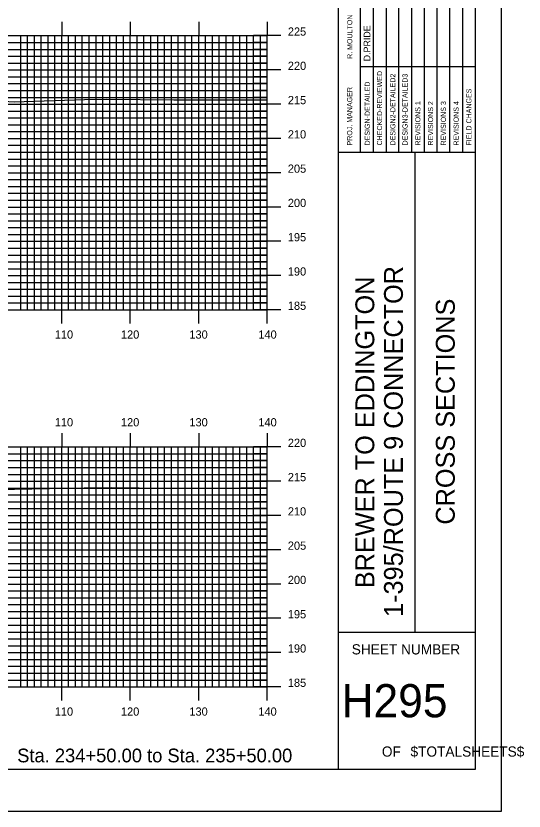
# Model space of a CAD drawing. Extents: x 1800355 to 1800699, y 442591 to 442811.
# Drawn here: x 1800624.3 to 1800698.5, y 442590.5 to 442706.6 of the extents above; entities that cross this region are included whole.
import ezdxf

# ---------------------------------------------------------------- set-up
doc = ezdxf.new("R2010")
doc.units = 0
for name, color, linetype in [('BORDER', 7, 'Continuous'), ('H_V ANNOTATION', 7, 'Continuous'), ('MAJOR', 7, 'Continuous'), ('MINOR', 7, 'Continuous'), ('PLOT BOUNDARY', 7, 'Continuous'), ('S_Roadway_Centerline', 7, 'Continuous')]:
    doc.layers.add(name, color=color, linetype=linetype)

msp = doc.modelspace()

# ---------------------------------------------------------------- linework, layer by layer
at = {"layer": 'BORDER'}
for p, q in [((1800671.44, 442596.67), (1800671.44, 442806.67)), ((1800671.44, 442686.67), (1800691.44, 442686.67)), ((1800682.62, 442616.67), (1800682.62, 442686.67)), ((1800671.44, 442616.67), (1800691.44, 442616.67))]:
    msp.add_line(p, q, dxfattribs=at)
msp.add_lwpolyline([(1800371.44, 442596.67), (1800691.44, 442596.67), (1800691.44, 442806.67), (1800371.44, 442806.67)], close=True, dxfattribs=at)
for points in [[(1800676.53, 442686.68), (1800676.53, 442721.67)], [(1800678.39, 442721.67), (1800678.39, 442686.68)], [(1800680.26, 442686.68), (1800680.26, 442721.67)], [(1800682.12, 442686.68), (1800682.12, 442721.67)], [(1800683.98, 442686.68), (1800683.98, 442721.67)], [(1800685.85, 442686.68), (1800685.85, 442721.67)], [(1800687.71, 442686.68), (1800687.71, 442721.67)], [(1800689.57, 442686.68), (1800689.57, 442721.67)], [(1800674.67, 442686.68), (1800674.67, 442720.26)], [(1800674.67, 442699.17), (1800691.44, 442699.17)]]:
    msp.add_lwpolyline(points, dxfattribs=at)
at = {"layer": 'MAJOR'}
for p, q in [((1800631.04, 442705.67), (1800631.04, 442703.67)), ((1800641.04, 442705.67), (1800641.04, 442703.67)), ((1800651.04, 442705.67), (1800651.04, 442703.67)), ((1800661.04, 442705.67), (1800661.04, 442703.67)), ((1800381.04, 442703.67), (1800661.04, 442703.67)), ((1800381.04, 442703.67), (1800661.04, 442703.67)), ((1800631.04, 442663.67), (1800631.04, 442703.67)), ((1800641.04, 442663.67), (1800641.04, 442703.67)), ((1800651.04, 442663.67), (1800651.04, 442703.67)), ((1800663.04, 442703.67), (1800659.03, 442703.67)), ((1800661.04, 442663.67), (1800661.04, 442703.67)), ((1800661.04, 442663.67), (1800661.04, 442703.67)), ((1800381.04, 442698.67), (1800661.04, 442698.67)), ((1800663.04, 442698.67), (1800659.03, 442698.67)), ((1800381.04, 442693.67), (1800661.04, 442693.67)), ((1800663.04, 442693.67), (1800659.03, 442693.67)), ((1800381.04, 442688.67), (1800661.04, 442688.67)), ((1800663.04, 442688.67), (1800659.03, 442688.67)), ((1800381.04, 442683.67), (1800661.04, 442683.67)), ((1800663.04, 442683.67), (1800659.03, 442683.67)), ((1800381.04, 442678.67), (1800661.04, 442678.67)), ((1800663.04, 442678.67), (1800659.03, 442678.67)), ((1800381.04, 442673.67), (1800661.04, 442673.67)), ((1800663.04, 442673.67), (1800659.03, 442673.67)), ((1800381.04, 442668.67), (1800661.04, 442668.67)), ((1800663.04, 442668.67), (1800659.03, 442668.67)), ((1800381.04, 442663.67), (1800661.04, 442663.67)), ((1800381.04, 442663.67), (1800661.04, 442663.67)), ((1800631.04, 442661.66), (1800631.04, 442663.67)), ((1800641.04, 442661.66), (1800641.04, 442663.67)), ((1800651.04, 442661.66), (1800651.04, 442663.67)), ((1800663.04, 442663.67), (1800659.03, 442663.67)), ((1800661.04, 442661.66), (1800661.04, 442663.67)), ((1800631.04, 442645.67), (1800631.04, 442643.67)), ((1800641.04, 442645.67), (1800641.04, 442643.67)), ((1800651.04, 442645.67), (1800651.04, 442643.67)), ((1800661.04, 442645.67), (1800661.04, 442643.67)), ((1800381.04, 442643.67), (1800661.04, 442643.67)), ((1800381.04, 442643.67), (1800661.04, 442643.67)), ((1800631.04, 442608.67), (1800631.04, 442643.67)), ((1800641.04, 442608.67), (1800641.04, 442643.67)), ((1800651.04, 442608.67), (1800651.04, 442643.67)), ((1800663.04, 442643.67), (1800659.03, 442643.67)), ((1800661.04, 442608.67), (1800661.04, 442643.67)), ((1800661.04, 442608.67), (1800661.04, 442643.67)), ((1800381.04, 442638.67), (1800661.04, 442638.67)), ((1800663.04, 442638.67), (1800659.03, 442638.67)), ((1800381.04, 442633.67), (1800661.04, 442633.67)), ((1800663.04, 442633.67), (1800659.03, 442633.67)), ((1800381.04, 442628.67), (1800661.04, 442628.67)), ((1800663.04, 442628.67), (1800659.03, 442628.67)), ((1800381.04, 442623.67), (1800661.04, 442623.67)), ((1800663.04, 442623.67), (1800659.03, 442623.67)), ((1800381.04, 442618.67), (1800661.04, 442618.67)), ((1800663.04, 442618.67), (1800659.03, 442618.67)), ((1800381.04, 442613.67), (1800661.04, 442613.67)), ((1800663.04, 442613.67), (1800659.03, 442613.67)), ((1800381.04, 442608.67), (1800661.04, 442608.67)), ((1800381.04, 442608.67), (1800661.04, 442608.67)), ((1800631.04, 442606.66), (1800631.04, 442608.67)), ((1800641.04, 442606.66), (1800641.04, 442608.67)), ((1800651.04, 442606.66), (1800651.04, 442608.67)), ((1800663.04, 442608.67), (1800659.03, 442608.67)), ((1800661.04, 442606.66), (1800661.04, 442608.67))]:
    msp.add_line(p, q, dxfattribs=at)
at = {"layer": 'MINOR'}
for p, q in [((1800625.04, 442663.67), (1800625.04, 442703.67)), ((1800626.04, 442663.67), (1800626.04, 442703.67)), ((1800627.04, 442663.67), (1800627.04, 442703.67)), ((1800628.04, 442663.67), (1800628.04, 442703.67)), ((1800629.04, 442663.67), (1800629.04, 442703.67)), ((1800630.04, 442663.67), (1800630.04, 442703.67)), ((1800632.04, 442663.67), (1800632.04, 442703.67)), ((1800633.04, 442663.67), (1800633.04, 442703.67)), ((1800634.04, 442663.67), (1800634.04, 442703.67)), ((1800635.04, 442663.67), (1800635.04, 442703.67)), ((1800636.04, 442663.67), (1800636.04, 442703.67)), ((1800637.04, 442663.67), (1800637.04, 442703.67)), ((1800638.04, 442663.67), (1800638.04, 442703.67)), ((1800639.04, 442663.67), (1800639.04, 442703.67)), ((1800640.04, 442663.67), (1800640.04, 442703.67)), ((1800642.04, 442663.67), (1800642.04, 442703.67)), ((1800643.04, 442663.67), (1800643.04, 442703.67)), ((1800644.04, 442663.67), (1800644.04, 442703.67)), ((1800645.04, 442663.67), (1800645.04, 442703.67)), ((1800646.04, 442663.67), (1800646.04, 442703.67)), ((1800647.04, 442663.67), (1800647.04, 442703.67)), ((1800648.04, 442663.67), (1800648.04, 442703.67)), ((1800649.04, 442663.67), (1800649.04, 442703.67)), ((1800650.04, 442663.67), (1800650.04, 442703.67)), ((1800652.04, 442663.67), (1800652.04, 442703.67)), ((1800653.04, 442663.67), (1800653.04, 442703.67)), ((1800654.04, 442663.67), (1800654.04, 442703.67)), ((1800655.04, 442663.67), (1800655.04, 442703.67)), ((1800656.04, 442663.67), (1800656.04, 442703.67)), ((1800657.04, 442663.67), (1800657.04, 442703.67)), ((1800658.04, 442663.67), (1800658.04, 442703.67)), ((1800659.04, 442663.67), (1800659.04, 442703.67)), ((1800660.04, 442663.67), (1800660.04, 442703.67)), ((1800381.04, 442702.67), (1800661.04, 442702.67)), ((1800661.04, 442702.67), (1800659.03, 442702.67)), ((1800381.04, 442701.67), (1800661.04, 442701.67)), ((1800381.04, 442700.67), (1800661.04, 442700.67)), ((1800661.04, 442701.67), (1800659.03, 442701.67)), ((1800661.04, 442700.67), (1800659.03, 442700.67)), ((1800381.04, 442699.67), (1800661.04, 442699.67)), ((1800661.04, 442699.67), (1800659.03, 442699.67)), ((1800381.04, 442697.67), (1800661.04, 442697.67)), ((1800661.04, 442697.67), (1800659.03, 442697.67)), ((1800381.04, 442696.67), (1800661.04, 442696.67)), ((1800661.04, 442696.67), (1800659.03, 442696.67)), ((1800381.04, 442695.67), (1800661.04, 442695.67)), ((1800661.04, 442695.67), (1800659.03, 442695.67)), ((1800381.04, 442694.67), (1800661.04, 442694.67)), ((1800661.04, 442694.67), (1800659.03, 442694.67)), ((1800381.04, 442692.67), (1800661.04, 442692.67)), ((1800661.04, 442692.67), (1800659.03, 442692.67)), ((1800381.04, 442691.67), (1800661.04, 442691.67)), ((1800661.04, 442691.67), (1800659.03, 442691.67)), ((1800381.04, 442690.67), (1800661.04, 442690.67)), ((1800661.04, 442690.67), (1800659.03, 442690.67)), ((1800381.04, 442689.67), (1800661.04, 442689.67)), ((1800661.04, 442689.67), (1800659.03, 442689.67)), ((1800381.04, 442687.67), (1800661.04, 442687.67)), ((1800661.04, 442687.67), (1800659.03, 442687.67)), ((1800381.04, 442686.67), (1800661.04, 442686.67)), ((1800381.04, 442685.67), (1800661.04, 442685.67)), ((1800661.04, 442686.67), (1800659.03, 442686.67)), ((1800661.04, 442685.67), (1800659.03, 442685.67)), ((1800381.04, 442684.67), (1800661.04, 442684.67)), ((1800661.04, 442684.67), (1800659.03, 442684.67)), ((1800381.04, 442682.67), (1800661.04, 442682.67)), ((1800661.04, 442682.67), (1800659.03, 442682.67)), ((1800381.04, 442681.67), (1800661.04, 442681.67)), ((1800661.04, 442681.67), (1800659.03, 442681.67)), ((1800381.04, 442680.67), (1800661.04, 442680.67)), ((1800661.04, 442680.67), (1800659.03, 442680.67)), ((1800381.04, 442679.67), (1800661.04, 442679.67)), ((1800661.04, 442679.67), (1800659.03, 442679.67)), ((1800381.04, 442677.67), (1800661.04, 442677.67)), ((1800661.04, 442677.67), (1800659.03, 442677.67)), ((1800381.04, 442676.67), (1800661.04, 442676.67)), ((1800661.04, 442676.67), (1800659.03, 442676.67)), ((1800381.04, 442675.67), (1800661.04, 442675.67)), ((1800661.04, 442675.67), (1800659.03, 442675.67)), ((1800381.04, 442674.67), (1800661.04, 442674.67)), ((1800661.04, 442674.67), (1800659.03, 442674.67)), ((1800381.04, 442672.67), (1800661.04, 442672.67)), ((1800381.04, 442671.67), (1800661.04, 442671.67)), ((1800661.04, 442672.67), (1800659.03, 442672.67)), ((1800661.04, 442671.67), (1800659.03, 442671.67)), ((1800381.04, 442670.67), (1800661.04, 442670.67)), ((1800661.04, 442670.67), (1800659.03, 442670.67)), ((1800381.04, 442669.67), (1800661.04, 442669.67)), ((1800661.04, 442669.67), (1800659.03, 442669.67)), ((1800381.04, 442667.67), (1800661.04, 442667.67)), ((1800661.04, 442667.67), (1800659.03, 442667.67)), ((1800381.04, 442666.67), (1800661.04, 442666.67)), ((1800661.04, 442666.67), (1800659.03, 442666.67)), ((1800381.04, 442665.67), (1800661.04, 442665.67)), ((1800381.04, 442664.67), (1800661.04, 442664.67)), ((1800661.04, 442665.67), (1800659.03, 442665.67)), ((1800661.04, 442664.67), (1800659.03, 442664.67)), ((1800381.04, 442642.67), (1800661.04, 442642.67)), ((1800625.04, 442608.67), (1800625.04, 442643.67)), ((1800626.04, 442608.67), (1800626.04, 442643.67)), ((1800627.04, 442608.67), (1800627.04, 442643.67)), ((1800628.04, 442608.67), (1800628.04, 442643.67)), ((1800629.04, 442608.67), (1800629.04, 442643.67)), ((1800630.04, 442608.67), (1800630.04, 442643.67)), ((1800632.04, 442608.67), (1800632.04, 442643.67)), ((1800633.04, 442608.67), (1800633.04, 442643.67)), ((1800634.04, 442608.67), (1800634.04, 442643.67)), ((1800635.04, 442608.67), (1800635.04, 442643.67)), ((1800636.04, 442608.67), (1800636.04, 442643.67)), ((1800637.04, 442608.67), (1800637.04, 442643.67)), ((1800638.04, 442608.67), (1800638.04, 442643.67)), ((1800639.04, 442608.67), (1800639.04, 442643.67)), ((1800640.04, 442608.67), (1800640.04, 442643.67)), ((1800642.04, 442608.67), (1800642.04, 442643.67)), ((1800643.04, 442608.67), (1800643.04, 442643.67)), ((1800644.04, 442608.67), (1800644.04, 442643.67)), ((1800645.04, 442608.67), (1800645.04, 442643.67)), ((1800646.04, 442608.67), (1800646.04, 442643.67)), ((1800647.04, 442608.67), (1800647.04, 442643.67)), ((1800648.04, 442608.67), (1800648.04, 442643.67)), ((1800649.04, 442608.67), (1800649.04, 442643.67)), ((1800650.04, 442608.67), (1800650.04, 442643.67)), ((1800652.04, 442608.67), (1800652.04, 442643.67)), ((1800653.04, 442608.67), (1800653.04, 442643.67)), ((1800654.04, 442608.67), (1800654.04, 442643.67)), ((1800655.04, 442608.67), (1800655.04, 442643.67)), ((1800656.04, 442608.67), (1800656.04, 442643.67)), ((1800657.04, 442608.67), (1800657.04, 442643.67)), ((1800658.04, 442608.67), (1800658.04, 442643.67)), ((1800661.04, 442642.67), (1800659.03, 442642.67)), ((1800659.04, 442608.67), (1800659.04, 442643.67)), ((1800660.04, 442608.67), (1800660.04, 442643.67)), ((1800381.04, 442641.67), (1800661.04, 442641.67)), ((1800661.04, 442641.67), (1800659.03, 442641.67)), ((1800381.04, 442640.67), (1800661.04, 442640.67)), ((1800661.04, 442640.67), (1800659.03, 442640.67)), ((1800381.04, 442639.67), (1800661.04, 442639.67)), ((1800661.04, 442639.67), (1800659.03, 442639.67)), ((1800381.04, 442637.67), (1800661.04, 442637.67)), ((1800661.04, 442637.67), (1800659.03, 442637.67)), ((1800381.04, 442636.67), (1800661.04, 442636.67)), ((1800381.04, 442635.67), (1800661.04, 442635.67)), ((1800661.04, 442636.67), (1800659.03, 442636.67)), ((1800661.04, 442635.67), (1800659.03, 442635.67)), ((1800381.04, 442634.67), (1800661.04, 442634.67)), ((1800661.04, 442634.67), (1800659.03, 442634.67)), ((1800381.04, 442632.67), (1800661.04, 442632.67)), ((1800661.04, 442632.67), (1800659.03, 442632.67)), ((1800381.04, 442631.67), (1800661.04, 442631.67)), ((1800661.04, 442631.67), (1800659.03, 442631.67)), ((1800381.04, 442630.67), (1800661.04, 442630.67)), ((1800661.04, 442630.67), (1800659.03, 442630.67)), ((1800381.04, 442629.67), (1800661.04, 442629.67)), ((1800661.04, 442629.67), (1800659.03, 442629.67)), ((1800381.04, 442627.67), (1800661.04, 442627.67)), ((1800661.04, 442627.67), (1800659.03, 442627.67)), ((1800381.04, 442626.67), (1800661.04, 442626.67)), ((1800661.04, 442626.67), (1800659.03, 442626.67)), ((1800381.04, 442625.67), (1800661.04, 442625.67)), ((1800661.04, 442625.67), (1800659.03, 442625.67)), ((1800381.04, 442624.67), (1800661.04, 442624.67)), ((1800661.04, 442624.67), (1800659.03, 442624.67)), ((1800381.04, 442622.67), (1800661.04, 442622.67)), ((1800661.04, 442622.67), (1800659.03, 442622.67)), ((1800381.04, 442621.67), (1800661.04, 442621.67)), ((1800381.04, 442620.67), (1800661.04, 442620.67)), ((1800661.04, 442621.67), (1800659.03, 442621.67)), ((1800661.04, 442620.67), (1800659.03, 442620.67)), ((1800381.04, 442619.67), (1800661.04, 442619.67)), ((1800661.04, 442619.67), (1800659.03, 442619.67)), ((1800381.04, 442617.67), (1800661.04, 442617.67)), ((1800661.04, 442617.67), (1800659.03, 442617.67)), ((1800381.04, 442616.67), (1800661.04, 442616.67)), ((1800661.04, 442616.67), (1800659.03, 442616.67)), ((1800381.04, 442615.67), (1800661.04, 442615.67)), ((1800661.04, 442615.67), (1800659.03, 442615.67)), ((1800381.04, 442614.67), (1800661.04, 442614.67)), ((1800661.04, 442614.67), (1800659.03, 442614.67)), ((1800381.04, 442612.67), (1800661.04, 442612.67)), ((1800661.04, 442612.67), (1800659.03, 442612.67)), ((1800381.04, 442611.67), (1800661.04, 442611.67)), ((1800661.04, 442611.67), (1800659.03, 442611.67)), ((1800381.04, 442610.67), (1800661.04, 442610.67)), ((1800661.04, 442610.67), (1800659.03, 442610.67)), ((1800381.04, 442609.67), (1800661.04, 442609.67)), ((1800661.04, 442609.67), (1800659.03, 442609.67))]:
    msp.add_line(p, q, dxfattribs=at)
at = {"layer": 'PLOT BOUNDARY'}
msp.add_lwpolyline([(1800355.25, 442590.55), (1800695.25, 442590.55), (1800695.25, 442810.55), (1800355.25, 442810.55)], close=True, dxfattribs=at)
at = {"layer": 'S_Roadway_Centerline'}
for points in [[(1800568.72, 442694.12), (1800587.56, 442694.01), (1800589.22, 442693.94), (1800590.86, 442694.02), (1800608.06, 442694.55), (1800612.32, 442694.7), (1800613.24, 442694.68), (1800624.11, 442694), (1800634.35, 442694.35), (1800637.64, 442694.4), (1800647.4, 442694.33), (1800657.45, 442694.31), (1800659.1, 442694.32), (1800660.86, 442694.31), (1800661.04, 442694.31)], [(1800571.52, 442637.59), (1800590.67, 442637.52), (1800594.97, 442637.47), (1800610.98, 442637.33), (1800619.04, 442637.41), (1800634.29, 442637.71), (1800638.24, 442637.76), (1800642.34, 442637.72), (1800649.15, 442637.66), (1800657.16, 442637.72), (1800661.04, 442637.72)]]:
    msp.add_lwpolyline(points, dxfattribs=at)

# ---------------------------------------------------------------- texts
at = {"layer": 'BORDER'}
for s, height, p in [('R. MOULTON', 0.745, (1800673.45, 442700.28)), ('D.PRIDE', 0.969, (1800676.08, 442699.92)), ('CHECKED-REVIEWED', 0.7455, (1800677.8, 442687.65)), ('DESIGN2-DETAILED2', 0.7455, (1800679.74, 442687.65)), ('DESIGN3-DETAILED3', 0.7455, (1800681.52, 442687.65)), ('DESIGN-DETAILED', 0.7455, (1800676.01, 442687.65)), ('PROJ. MANAGER', 0.7455, (1800673.44, 442687.65)), ('FIELD CHANGES', 0.7455, (1800690.84, 442687.65)), ('REVISIONS 1', 0.7455, (1800683.39, 442687.65)), ('REVISIONS 2', 0.7455, (1800685.25, 442687.65)), ('REVISIONS 3', 0.7455, (1800687.12, 442687.65)), ('REVISIONS 4', 0.7455, (1800688.98, 442687.65)), ('1-395/ROUTE 9 CONNECTOR', 2.7557, (1800680.84, 442618.87)), ('BREWER TO EDDINGTON', 2.7557, (1800676.66, 442623.07)), ('CROSS SECTIONS', 2.7557, (1800688.41, 442632.34))]:
    msp.add_text(s, height=height, rotation=90, dxfattribs=at).set_placement(p)
for s, height, p in [('SHEET NUMBER', 1.4905, (1800673.37, 442613.4)), ('H295', 4.839, (1800671.88, 442604.23)), ('OF', 1.491, (1800677.77, 442598.49)), ('$TOTALSHEETS$', 1.4905, (1800681.95, 442598.49))]:
    msp.add_text(s, height=height, dxfattribs=at).set_placement(p)
at = {"layer": 'H_V ANNOTATION'}
for s, height, p in [('225', 1.2, (1800664.04, 442703.67)), ('220', 1.2, (1800664.04, 442698.67)), ('215', 1.2, (1800664.04, 442693.67)), ('210', 1.2, (1800664.04, 442688.67)), ('205', 1.2, (1800664.04, 442683.67)), ('200', 1.2, (1800664.04, 442678.67)), ('195', 1.2, (1800664.04, 442673.67)), ('190', 1.2, (1800664.04, 442668.67)), ('185', 1.2, (1800664.04, 442663.67)), ('110', 1.2, (1800630.02, 442659.47)), ('120', 1.2, (1800639.68, 442659.47)), ('130', 1.2, (1800649.67, 442659.47)), ('140', 1.2, (1800659.74, 442659.47)), ('110', 1.2, (1800630.02, 442646.67)), ('120', 1.2, (1800639.68, 442646.67)), ('130', 1.2, (1800649.67, 442646.67)), ('140', 1.2, (1800659.74, 442646.67)), ('220', 1.2, (1800664.04, 442643.67)), ('215', 1.2, (1800664.04, 442638.67)), ('210', 1.2, (1800664.04, 442633.67)), ('205', 1.2, (1800664.04, 442628.67)), ('200', 1.2, (1800664.04, 442623.67)), ('195', 1.2, (1800664.04, 442618.67)), ('190', 1.2, (1800664.04, 442613.67)), ('185', 1.2, (1800664.04, 442608.67)), ('110', 1.2, (1800630.02, 442604.47)), ('120', 1.2, (1800639.68, 442604.47)), ('130', 1.2, (1800649.67, 442604.47)), ('140', 1.2, (1800659.74, 442604.47)), ('Sta. 234+50.00 to Sta. 235+50.00', 2.0004, (1800624.53, 442597.66))]:
    msp.add_text(s, height=height, dxfattribs=at).set_placement(p)

doc.saveas('drawing.dxf')
